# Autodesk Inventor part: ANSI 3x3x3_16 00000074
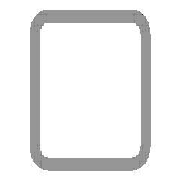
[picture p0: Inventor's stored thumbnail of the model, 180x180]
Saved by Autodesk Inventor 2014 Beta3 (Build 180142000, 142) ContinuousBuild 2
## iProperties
IsCustomPart: 1
_CCFamilyMember: 9
_CCFamilyDisplayName: ANSI AISC (Square) - Tube
_FrameMemberDoc: Frame Member File
_Version: 15.0.0
_GetPNFromCC: 1
Created: 2011-01
Part Number: ANSI 3x3x3_16 00000074
Material: Steel, Mild
Description: Tube
Document SubType Name: Modeling
Standard: ANSI
Designer: Beta-8540w
Standards Organization: ANSI
Language: en-US
Size Designation: 3x3x3/16
Categories: <MemberInstance><Categories><Category DisplayName="Structural Shapes" InternalName="089c4875-fa83-4c05-b084-43b9cc11f5ed" Mnemonic="GRDR"><CategoryParameter Dis
Stock Number: 3x3x3/16
Density: 7.86 g/cm^3
Appearance: Steel
G_L: 58.775 in
G_W: 3.000 in
G_H: 3.000 in
+AE3CA65D-4403-45DE-BD14-7280831DFD21+CUTDETAIL1: Cut
Author: Beta-8540w
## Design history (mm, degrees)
node "Start plane"
node "End plane"
sketch "Sketch"
  geometry: L1 (-38.1, -28.575)-(-38.1, 28.575); L2 (-28.575, 38.1)-(28.575, 38.1); L3 (38.1, 28.575)-(38.1, -28.575); L4 (28.575, -38.1)-(-28.575, -38.1); L5 (-28.575, 33.337)-(28.575, 33.338); L6 (33.338, 28.575)-(33.338, -28.575); L7 (28.575, -33.337)-(-28.575, -33.338); L8 (-33.338, -28.575)-(-33.338, 28.575); L9 (0, 56.102)-(0, -56.102) reference; L10 (-56.102, 0)-(56.102, 0) reference; A1 r 9.525 centre (-28.575, -28.575) between (-38.1, -28.575) and (-28.575, -38.1); A2 r 9.525 centre (-28.575, 28.575) between (-28.575, 38.1) and (-38.1, 28.575); A3 r 9.525 centre (28.575, 28.575) between (38.1, 28.575) and (28.575, 38.1); A4 r 9.525 centre (28.575, -28.575) between (28.575, -38.1) and (38.1, -28.575); A5 r 4.763 centre (-28.575, 28.575) between (-28.575, 33.337) and (-33.338, 28.575); A6 r 4.763 centre (28.575, 28.575) between (33.338, 28.575) and (28.575, 33.338); A7 r 4.763 centre (28.575, -28.575) between (28.575, -33.337) and (33.338, -28.575); A8 r 4.763 centre (-28.575, -28.575) between (-33.338, -28.575) and (-28.575, -33.338)
  constraints: 16 end point, 16 point on circle, 8 centre point, 8 tangent, 4 parallel, 3 equal radius, 2 perpendicular, 7 other
  dimensions: "d10" = 76.2 distance between parallel lines of L2 L4 (= G_H); "d11" = 76.2 distance between parallel lines of L1 L3 (= G_W); "d12" = 4.7625 distance between parallel lines of L3 L6 (= G_T); "d15" = 38.1 distance between parallel lines of L2 L10 (= 0.5 x d10); "d16" = 38.1 distance between parallel lines of L9 L3 (= 0.5 x d11); "d17" = 9.525 radius of A1 (= G_IR)
extrude "Body" new body sketch "Sketch" stored distance "d3" = 1492.89148 (= G_L); taper "d4" = 0 deg
node "Driven Length"
  sketch "Sketch3"
    geometry: L1 (0, 0)-(10, 0) reference
    constraints: 2 end point, 1 horizontal
  workplane "Work Plane3"
  sketch "Sketch4"
    geometry: L1 (-2, 0)-(12, 0) reference; L2 (-2, 1492.891)-(12, 1492.891) reference
    dimensions: "d19" = 1492.89148 distance between parallel lines of L1 L2 (derived)
workplane "Work Plane4"
split "Split1"
body "Solid1"
other parameters: "G_W" = 76.2 [user parameter; used in 1 equation term], "G_H" = 76.2 [user parameter; used in 1 equation term], "G_T" = 4.7625 [user parameter; used in 1 equation term], "G_IR" = 9.525 [user parameter; used in 1 equation term], "G_L" = 1492.89148 (= d19) [user parameter; used in 1 equation term], "G_OFFSET_START" = 0 [user parameter; used in 1 equation term], "G_OFFSET_END" = -31.10852 [user parameter; used in 1 equation term], "d13" = 0 (computed from G_OFFSET_START), "d14" = 1492.89148 (= G_OFFSET_END + B_L), "B_L" = 1524 [user parameter; used in 1 equation term], "d18" = 90 deg
